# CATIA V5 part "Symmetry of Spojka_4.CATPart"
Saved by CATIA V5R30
Part number: Symmetry of Spojka_4
Bounding box of the stored display mesh (mm): x -8.66 to 8.66, y -7.5 to 7.5, z -9 to 17
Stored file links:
  E:\Bakalarka\Model\Forma_v7\Symmetry of Spojka_4.CATPart
  E:\Bakalarka\Model\Forma_v7\Spojka_1.CATPart
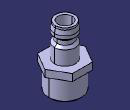
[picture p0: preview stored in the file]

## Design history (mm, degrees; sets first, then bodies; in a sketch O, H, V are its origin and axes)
Body1 (main body)
  Body2 "Body from original PartBody"
    Solid1: linked copy from another document
  Assemble1: tool Body2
